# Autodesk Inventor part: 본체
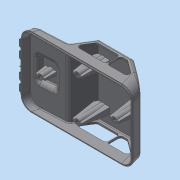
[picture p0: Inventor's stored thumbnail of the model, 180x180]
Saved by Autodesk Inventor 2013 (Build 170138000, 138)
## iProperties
Created: 2015-05
Part Number: 본체
Material: 일반
Document SubType Name: Modeling
Designer: Administrator
Density: 1 g/cm^3
Author: Administrator
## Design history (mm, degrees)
sketch "스케치1"
  geometry: L1 (0, 0)-(122, 0); L2 (0, 0)-(1.608, 6); L3 (55.441, 31)-(92, 31); L4 (54.497, 31)-(55.441, 31); L5 (42, 11)-(54.497, 31); L6 (122, 0)-(122, 11); L7 (42, 11)-(2.391, 8.924); L8 (2.391, 8.924)-(1.474, 5.5); L9 (122, 0)-(119.053, 11); L10 (119.053, 11)-(92, 31); 1 further point
  constraints: 20 end point, 2 horizontal, 2 point on line, 1 coincident, 1 parallel, 1 perpendicular
  dimensions: "d0" = 122 distance of L1.start L1.end; "d1" = 105 deg angle of L2 L1; "d3" = 5 vertical distance of L5.start L2.end; "d9" = 6 vertical distance of point (0, 0) L2.end; "d19" = 3 deg angle of L1 L7; "d20" = 42 horizontal distance of L5.start point (0, 0); "d21" = 125 deg angle of L5 L7; "d42" = 31 distance between parallel lines of L1 L3; "d43" = 105 deg angle of L1 L9; "d44" = 20 vertical distance of L9.end L3.end; "d45" = 30 horizontal distance of L6.end L3.end
extrude "돌출1" new body sketch "스케치1" stored distance "d11" = 76; taper "d12" = 0 deg
sketch "스케치20"
  geometry: 1 further point
node "작업 평면6"
  node "작업 평면5"
sketch "스케치3"
  geometry: L1 (8.145, 51)-(28.145, 51); L2 (28.145, 51)-(28.145, 25); L3 (28.145, 25)-(8.145, 25); L4 (8.145, 25)-(8.145, 51); L5 (-2.855, 0)-(-2.855, 76) reference; 2 further points
  constraints: 8 end point, 2 parallel, 1 horizontal, 1 horizontal alignment, 1 midpoint, 1 perpendicular
  dimensions: "d22" = 20 distance of L1.start L1.end; "d24" = 26 distance of L3.end L1.start; "d25" = 11 distance from line of L1.start L5
extrude "돌출3" join sketch "스케치3" distance "d26" = 5; taper "d27" = 0 deg
fillet "모깎기1" dims "d28" = 12
fillet "모깎기2" dims "d30" = 3
fillet "모깎기3" dims "d31" = 3
fillet "모깎기4" dims "d32" = 3, "d33" = 3
fillet "모깎기6" dims "d46" = 3, "d47" = 12
sketch "스케치7"
  geometry: L1 (104.807, 17.801)-(109.577, 0) reference; L2 (45.372, 10.735)-(56.16, 28) reference; L3 (12.423, 0)-(109.577, 0) reference; L4 (47.896, 11)-(57.269, 26); L5 (90.352, 26)-(105.638, 14.699); L6 (57.269, 26)-(81.896, 26); L7 (82.642, 26)-(90.352, 26); L8 (53.616, 29.59)-(42.828, 12.324) reference; L9 (91.011, 31)-(56.16, 31) reference; L10 (106.59, 20.213)-(92.795, 30.412) reference; L11 (12.423, 0)-(0, 0) reference; L12 (122, 0)-(109.577, 0) reference; L13 (47.896, 11)-(81.896, 11); L14 (81.896, 26)-(81.896, 11); L15 (82.642, 26)-(82.642, 11); L16 (82.642, 11)-(103.794, 11); L17 (103.794, 11)-(110.642, 11); L18 (105.638, 14.699)-(110.642, 11)
  constraints: 21 end point, 7 parallel, 3 collinear, 2 perpendicular, 1 point on line
  dimensions: "d48" = 5 distance between parallel lines of L4 L8; "d49" = 5 distance between parallel lines of L7 L9; "d54" = 5 distance between parallel lines of L10 L5; "d55" = 15 vertical distance of L4.start L4.end; "d57" = 34 distance of L13.end L4.start; "d58" = 28 distance of L17.end L15.end
feature "쉘1" dims "d29" = 2
extrude "돌출4" cut sketch "스케치7" distance "d59" = 10; taper "d60" = 0 deg
fillet "모깎기7" dims "d61" = 3
fillet "모깎기8" dims "d62" = 3
sketch "스케치9"
  geometry: L1 (12.423, 64)-(109.577, 64) reference; L2 (0, 52)-(0, 0) reference; L3 (109.577, -12)-(12.423, -12) reference; L4 (122, 0)-(122, 52) reference; L5 (121, 52)-(121, 0); L6 (109.577, -11)-(12.423, -11); L7 (1, 0)-(1, 52); L8 (12.423, 63)-(109.577, 63); 5 further points; 4 other entities
  constraints: 8 end point, 7 parallel, 16 other
  dimensions: "d67" = 1 distance between parallel lines of L4 L5
extrude "돌출6" cut sketch "스케치9" distance "d68" = 1; taper "d69" = 0 deg
node "작업 평면1"
sketch "스케치10"
  geometry: A1 r 4 centre (-1, -21) between (-1, -17) and (-1, -25); A2 r 4 centre (-1, -10) between (-1, -6) and (-1, -14); A3 r 4 centre (-1, 10) between (-1, 14) and (-1, 6); A4 r 4 centre (-1, 21) between (-1, 25) and (-1, 17); 3 further points
  constraints: 8 point on circle, 4 centre point, 3 vertical alignment, 9 other
  dimensions: "d71" = 8 diameter of A1; "d72" = 8 diameter of A2; "d73" = 8 diameter of A3; "d74" = 8 diameter of A4; "d75" = 1 horizontal distance of point (0, 0) A2.centre; "d76" = 11 distance of A2.centre A1.centre; "d77" = 11 distance of A4.centre A3.centre; "d78" = 20 distance of A3.centre A2.centre; "d79" = 10 vertical distance of point (0, 0) A2.centre
extrude "돌출7" join sketch "스케치10" stored distance "d80" = 1; taper "d81" = 0 deg
chamfer "모따기1" distance "d82" = 1; stored, may be unused: second distance "d83" = 2, angle "d84" = 45 deg
chamfer "모따기2" distance "d85" = 1; stored, may be unused: second distance "d86" = 2, angle "d87" = 45 deg
sketch "스케치11"
  geometry: L1 (65.572, 9)-(65.572, 61) reference; 2 further points
  constraints: 1 horizontal alignment, 1 other
  dimensions: "d88" = 50 distance from line of L1 point (15.572, 35)
feature "엠보싱1" sketch "스케치11" dims "d0" = 122, "d1" = 105 deg, "d3" = 5, "d9" = 6, "d19" = 3 deg, "d20" = 42, "d21" = 125 deg, "d42" = 31, "d43" = 105 deg, "d44" = 20, "d45" = 30, "d89" = 0.5, "d90" = 0
node "작업 평면2"
sketch "스케치13"
  geometry: L1 (121.732, 26)-(121.732, -26) reference; C1 r 3 at (100.732, 0); C2 r 3 at (60.732, -22); C3 r 3 at (20.732, 0); 1 further point
  constraints: 3 centre point, 2 horizontal alignment
  dimensions: "d92" = 6 diameter of C1; "d93" = 6 diameter of C2; "d94" = 6 diameter of C3; "d95" = 21 distance from line of C1.centre L1; "d96" = 40 horizontal distance of C2.centre C1.centre; "d97" = 40 horizontal distance of C3.centre C2.centre; "d98" = 22 vertical distance of C2.centre point (0, 0)
extrude "돌출8" join sketch "스케치13" stored distance "d99" = 2; taper "d100" = 2 deg
sketch "스케치16"
  geometry: 1 further point
sketch "스케치17"
  geometry: L1 (-5, 1)-(5, 1); L2 (5, 1)-(5, -1); L3 (5, -1)-(-5, -1); L4 (-5, -1)-(-5, 1); L5 (35, 23)-(45, 23); L6 (45, 23)-(45, 21); L7 (45, 21)-(35, 21); L8 (35, 21)-(35, 23); L9 (-35, 23)-(-45, 23); L10 (-45, 23)-(-45, 21); L11 (-45, 21)-(-35, 21); L12 (-35, 21)-(-35, 23); C1 r 3 at (0, 0) reference; C2 r 3 at (-40, 22) reference; C3 r 3 at (40, 22) reference; 7 further points
  constraints: 24 end point, 8 parallel, 6 midpoint, 3 horizontal, 3 horizontal alignment, 3 perpendicular, 3 vertical alignment
  dimensions: "d104" = 2 distance of L1.end L2.end; "d106" = 10 distance of L1.start L1.end; "d107" = 10 distance of L5.start L5.end; "d108" = 10 distance of L9.start L9.end
  node "투영된 루프3"
  node "투영된 루프4"
extrude "돌출10" join sketch "스케치17" stored distance "d109" = 2; taper "d110" = 5 deg
sketch "스케치19"
  geometry: L1 (65.732, 23)-(63.56, 23) reference; L2 (57.904, 23)-(55.732, 23) reference; L3 (55.732, 23)-(55.732, 21) reference; L4 (55.732, 21)-(57.904, 21) reference; L5 (63.56, 21)-(65.732, 21) reference; L6 (65.732, 21)-(65.732, 23) reference; L7 (105.732, -1)-(103.56, -1) reference; L8 (105.732, 1)-(105.732, -1) reference; L9 (103.56, 1)-(105.732, 1) reference; L10 (95.732, 1)-(97.904, 1) reference; L11 (95.732, -1)-(95.732, 1) reference; L12 (97.904, -1)-(95.732, -1) reference; L13 (65.732, -23)-(63.56, -23) reference; L14 (65.732, -21)-(65.732, -23) reference; L15 (63.56, -21)-(65.732, -21) reference; L16 (55.732, -21)-(57.904, -21) reference; L17 (55.732, -23)-(55.732, -21) reference; L18 (57.904, -23)-(55.732, -23) reference; A1 r 3 centre (20.732, 0) between (17.904, -1) and (23.56, -1) reference; A2 r 3 centre (60.732, 22) between (63.56, 23) and (57.904, 23) reference; A3 r 3 centre (60.732, 22) between (57.904, 21) and (63.56, 21) reference; A4 r 3 centre (100.732, 0) between (97.904, -1) and (103.56, -1) reference; A5 r 3 centre (100.732, 0) between (103.56, 1) and (97.904, 1) reference; A6 r 3 centre (60.732, -22) between (57.904, -23) and (63.56, -23) reference; A7 r 3 centre (60.732, -22) between (63.56, -21) and (57.904, -21) reference; 1 further point
hole "구멍1" sketch "스케치19" at (60.732, 22), (100.732, 0), (60.732, -22), (20.732, 0) diameter "d111" = 3.242; stored, may be unused: countersink angle "d115" = 90 deg, drill point angle "d117" = 118 deg; dims "d112" = 9, "d113" = 4, "d114" = 2, "d116" = 11
sketch "스케치21"
  geometry: L1 (5, 1)-(2.828, 1) reference; L2 (-2.828, 1)-(-5, 1) reference; L3 (-5, 1)-(-5, -1) reference; L4 (-5, -1)-(-2.828, -1) reference; L5 (2.828, -1)-(5, -1) reference; L6 (5, -1)-(5, 1) reference; C1 r 1.621 at (0, 0) reference; A1 r 3 centre (0, 0) between (2.828, 1) and (-2.828, 1) reference; A2 r 3 centre (0, 0) between (-2.828, -1) and (2.828, -1) reference; 1 further point
node "솔리드1"
mirror "대칭1"
mirror "대칭2"
node "투영된 루프5"
node "투영된 루프6"
node "투영된 루프7"
node "작업 평면4"
other parameters: "d70" = -2, "d91" = 1, "d118" = 0, "d119" = -15 deg, "d120" = 38
